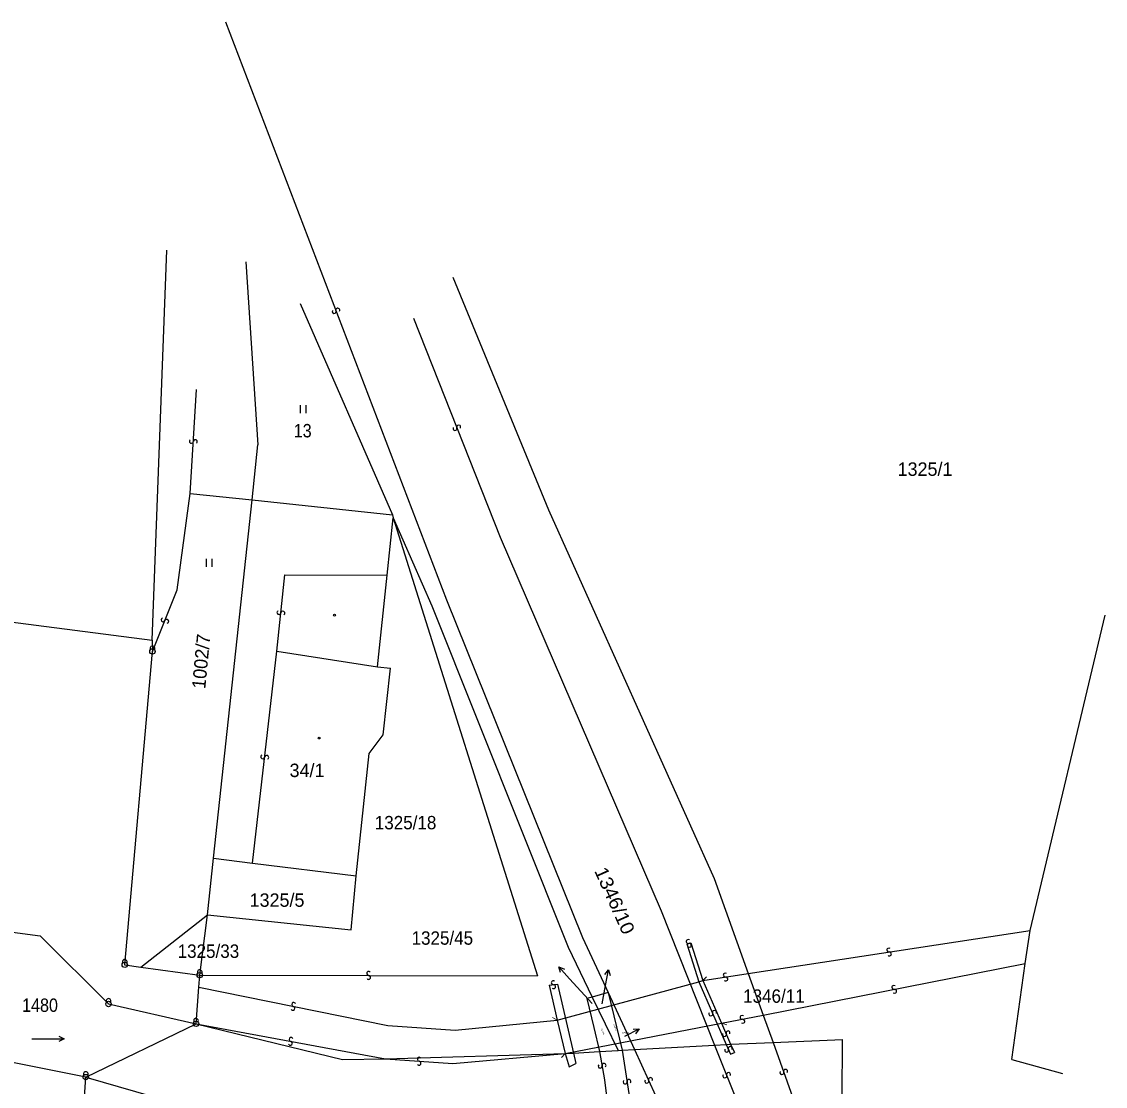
# Model space of a CAD drawing. Extents: x -871901 to -870967, y -1075952 to -1074892.
# Drawn here: x -871136.9 to -871056.1, y -1075219.4 to -1075139.9 of the extents above; entities that cross this region are included whole.
import ezdxf
from ezdxf.enums import TextEntityAlignment as Align

# ---------------------------------------------------------------- set-up
doc = ezdxf.new("R2010")
doc.units = 0
doc.header["$LTSCALE"] = 0.4
for name, color, linetype, lineweight in [('1', 7, 'Continuous', 25), ('16', 7, 'Continuous', 25), ('24', 7, 'Continuous', 25), ('25', 7, 'Continuous', 25), ('26', 7, 'Continuous', 25), ('4', 7, 'Continuous', 25)]:
    doc.layers.add(name, color=color, linetype=linetype, lineweight=lineweight)
doc.layers.add('18', color=7, linetype='Continuous')
doc.layers.add('19', color=7, linetype='Continuous')

msp = doc.modelspace()

# ---------------------------------------------------------------- linework, layer by layer
at = {"layer": '1'}
for p, q in [((-871127.17, -1075186.06), (-871126.1, -1075156.97)), ((-871120.19, -1075157.85), (-871119.29, -1075171.49)), ((-871104.75, -1075159), (-871097.61, -1075176.34)), ((-871116.14, -1075160.96), (-871109.26, -1075176.73)), ((-871119.73, -1075175.61), (-871119.29, -1075171.49)), ((-871122.61, -1075202.33), (-871119.73, -1075175.61)), ((-871119.73, -1075175.61), (-871109.26, -1075176.73)), ((-871109.64, -1075181.21), (-871109.2, -1075176.94)), ((-871097.61, -1075176.34), (-871085.24, -1075203.86)), ((-871164.62, -1075181.27), (-871127.17, -1075186.06)), ((-871110.36, -1075188.06), (-871109.64, -1075181.21)), ((-871127.17, -1075186.06), (-871127.16, -1075186.91)), ((-871129.23, -1075210.29), (-871127.16, -1075186.91)), ((-871110.36, -1075188.06), (-871109.41, -1075188.17)), ((-871109.95, -1075193.13), (-871109.41, -1075188.17)), ((-871122.61, -1075202.33), (-871119.69, -1075202.71)), ((-871119.69, -1075202.71), (-871111.95, -1075203.66)), ((-871112.34, -1075207.69), (-871111.95, -1075203.66)), ((-871085.24, -1075203.86), (-871082.7, -1075210.94)), ((-871128.02, -1075210.46), (-871123.06, -1075206.55)), ((-871123.06, -1075206.55), (-871112.34, -1075207.69)), ((-871129.23, -1075210.29), (-871128.02, -1075210.46)), ((-871128.02, -1075210.46), (-871123.63, -1075211.06)), ((-871082.7, -1075210.94), (-871081.59, -1075214.04)), ((-871123.7, -1075211.96), (-871123.63, -1075211.06)), ((-871123.91, -1075214.69), (-871123.7, -1075211.96)), ((-871093.16, -1075212.36), (-871091.2, -1075216.61)), ((-871093.16, -1075212.36), (-871092.1, -1075216.66)), ((-871081.59, -1075214.04), (-871080.85, -1075216.08)), ((-871123.91, -1075214.69), (-871112.99, -1075217.35)), ((-871091.2, -1075216.61), (-871085.21, -1075216.27)), ((-871080.85, -1075216.08), (-871075.68, -1075215.86)), ((-871112.99, -1075217.35), (-871109.77, -1075217.3)), ((-871109.77, -1075217.3), (-871096.36, -1075216.91)), ((-871096.36, -1075216.91), (-871095.74, -1075216.87)), ((-871063.04, -1075217.35), (-871059.26, -1075218.39)), ((-871132.14, -1075218.66), (-871116.67, -1075223.11))]:
    msp.add_line(p, q, dxfattribs=at)
for points in [[(-871109.26, -1075176.73), (-871109.2, -1075176.94), (-871106.32, -1075183.51), (-871096.14, -1075208.96)], [(-871063.04, -1075217.35), (-871062.03, -1075210.19), (-871061.68, -1075207.72), (-871056.06, -1075184.2)], [(-871111.95, -1075203.66), (-871110.99, -1075194.53), (-871109.95, -1075193.13)], [(-871123.63, -1075211.06), (-871123.06, -1075206.55), (-871122.61, -1075202.33)], [(-871132.14, -1075218.66), (-871140.73, -1075216.95), (-871140.23, -1075207.5)], [(-871140.23, -1075207.5), (-871135.53, -1075208.13), (-871130.44, -1075213.21), (-871123.91, -1075214.69)], [(-871096.14, -1075208.96), (-871094.34, -1075212.69), (-871092.41, -1075216.68)], [(-871093.16, -1075212.36), (-871094.34, -1075212.69), (-871094.76, -1075212.8), (-871094.22, -1075214.97), (-871093.8, -1075216.76)], [(-871132.62, -1075226.11), (-871132.14, -1075218.66), (-871123.91, -1075214.69)], [(-871095.74, -1075216.87), (-871093.8, -1075216.76), (-871092.41, -1075216.68), (-871092.1, -1075216.66), (-871091.2, -1075216.61)], [(-871085.21, -1075216.27), (-871084.34, -1075216.22), (-871084.02, -1075216.21), (-871080.85, -1075216.08)], [(-871079.27, -1075220.49), (-871075.69, -1075220.23), (-871075.68, -1075215.86)]]:
    msp.add_lwpolyline(points, dxfattribs=at)
at = {"layer": '16'}
for p, q in [((-871096.04, -1075211.33), (-871096.844, -1075210.439)), ((-871093.36, -1075211.83), (-871093.141, -1075210.65)), ((-871094.36, -1075213.18), (-871096.04, -1075211.33)), ((-871093.61, -1075213.2), (-871093.36, -1075211.83)), ((-871091.91, -1075215.62), (-871090.84, -1075215.075))]:
    msp.add_line(p, q, dxfattribs=at)
for points in [[(-871096.724, -1075210.87), (-871096.844, -1075210.439), (-871096.427, -1075210.602)], [(-871093.41, -1075211.007), (-871093.141, -1075210.65), (-871093.017, -1075211.079)], [(-871091.287, -1075215.078), (-871090.84, -1075215.075), (-871091.106, -1075215.435)]]:
    msp.add_lwpolyline(points, dxfattribs=at)
at = {"layer": '24'}
for centre, radius in [((-871127.1595, -1075186.9095), 0.2005), ((-871127.1595, -1075186.9095), 0.00851), ((-871129.2295, -1075210.2895), 0.2005), ((-871129.2295, -1075210.2895), 0.00851), ((-871123.6295, -1075211.0595), 0.2005), ((-871123.6295, -1075211.0595), 0.00851), ((-871130.4395, -1075213.2095), 0.2005), ((-871130.4395, -1075213.2095), 0.00851), ((-871123.9095, -1075214.6895), 0.2005), ((-871123.9095, -1075214.6895), 0.00851), ((-871132.1395, -1075218.6595), 0.2005), ((-871132.1395, -1075218.6595), 0.00851)]:
    msp.add_circle(centre, radius, dxfattribs=at)
for centre in [(-871127.1598, -1075186.6836), (-871129.2298, -1075210.0636), (-871123.6298, -1075210.8336), (-871130.4398, -1075212.9836), (-871123.9098, -1075214.4636), (-871132.1398, -1075218.4336)]:
    msp.add_arc(centre, 0.1746, 328.19485, 209.95045, dxfattribs=at)
at = {"layer": '25'}
for p, q in [((-871116.106, -1075169.135), (-871116.106, -1075168.535)), ((-871115.693, -1075169.135), (-871115.693, -1075168.535)), ((-871123.126, -1075180.595), (-871123.126, -1075179.995)), ((-871122.713, -1075180.595), (-871122.713, -1075179.995)), ((-871136.15, -1075215.82), (-871133.749, -1075215.82))]:
    msp.add_line(p, q, dxfattribs=at)
msp.add_lwpolyline([(-871134.149, -1075215.619), (-871133.749, -1075215.82), (-871134.149, -1075216.02)], dxfattribs=at)
for centre in [(-871113.5795, -1075184.2095), (-871114.7295, -1075193.3695)]:
    msp.add_circle(centre, 0.0705, dxfattribs=at)
for centre, radius, start, end in [((-871113.6081, -1075161.5507), 0.1471, 148.03701, 19.58833), ((-871113.3321, -1075161.4484), 0.1472, 328.13804, 200.64859), ((-871104.5876, -1075170.2723), 0.1472, 149.23847, 20.58919), ((-871104.3126, -1075170.1668), 0.1473, 328.86146, 201.15112), ((-871124.2564, -1075171.239), 0.1468, 123.81387, 355.69416), ((-871123.9626, -1075171.2605), 0.1477, 304.23097, 176.67729), ((-871117.7261, -1075184.0129), 0.147, 121.73204, 353.36129), ((-871117.4332, -1075184.0461), 0.1477, 301.43196, 173.79242), ((-871126.3658, -1075184.5539), 0.1469, 105.96952, 337.62255), ((-871126.0938, -1075184.6661), 0.1473, 285.73428, 158.14591), ((-871118.926, -1075194.7716), 0.1471, 121.47472, 352.97441), ((-871118.6337, -1075194.8084), 0.1475, 300.89976, 173.35652), ((-871087.1817, -1075208.5488), 0.1473, 54.93118, 286.58962), ((-871087.0974, -1075208.8311), 0.1474, 234.37396, 106.96356), ((-871072.2109, -1075209.1843), 0.1472, 46.66657, 278.18725), ((-871072.1685, -1075209.4759), 0.1475, 225.82417, 98.36216), ((-871111.028, -1075210.9326), 0.1474, 37.15933, 269.22266), ((-871084.4209, -1075211.0543), 0.1472, 46.66657, 278.18725), ((-871111.0311, -1075211.2275), 0.1475, 217.02669, 89.61382), ((-871097.2547, -1075211.6235), 0.1472, 43.98721, 275.82854), ((-871097.2251, -1075211.9166), 0.1474, 223.34947, 95.58775), ((-871084.3785, -1075211.3459), 0.1475, 225.82417, 98.36216), ((-871071.8363, -1075211.9753), 0.1471, 48.43878, 280.16792), ((-871071.7831, -1075212.2649), 0.1474, 228.30368, 100.3659), ((-871116.6811, -1075213.5341), 0.1474, 205.69864, 77.85438), ((-871116.6194, -1075213.2461), 0.1471, 25.80808, 257.85296), ((-871085.4957, -1075213.9471), 0.1472, 150.64344, 22.70345), ((-871085.2246, -1075213.8321), 0.1473, 330.94838, 203.25141), ((-871083.1663, -1075214.2053), 0.1471, 48.43878, 280.16792), ((-871083.1131, -1075214.4949), 0.1474, 228.30368, 100.3659), ((-871116.8117, -1075215.8553), 0.1474, 26.99346, 259.07257), ((-871084.4859, -1075215.4869), 0.1474, 150.30454, 22.00339), ((-871084.2143, -1075215.3722), 0.1475, 330.40612, 203.09844), ((-871116.8686, -1075216.1444), 0.1472, 207.08914, 79.17619), ((-871084.3159, -1075216.6469), 0.1474, 150.30454, 22.00339), ((-871084.0446, -1075216.5321), 0.1473, 330.94838, 203.25141), ((-871107.2478, -1075217.3331), 0.1474, 33.57583, 265.33525), ((-871107.272, -1075217.627), 0.1475, 212.83023, 85.33669), ((-871093.7555, -1075217.8427), 0.1473, 137.20369, 8.0804), ((-871093.465, -1075217.795), 0.1472, 317.07802, 189.78392), ((-871080.1993, -1075218.3277), 0.1472, 147.17263, 18.35746), ((-871079.9209, -1075218.2313), 0.1474, 326.99271, 199.42006), ((-871091.8962, -1075219.0298), 0.1475, 135.82345, 7.13823), ((-871091.6042, -1075218.9889), 0.1473, 314.90348, 188.18653), ((-871090.2745, -1075218.9699), 0.1472, 151.70045, 23.42411), ((-871090.0055, -1075218.8494), 0.1475, 332.35817, 204.47779), ((-871084.4476, -1075218.5823), 0.1472, 149.23847, 20.58919), ((-871084.1726, -1075218.4768), 0.1473, 328.86146, 201.15112)]:
    msp.add_arc(centre, radius, start, end, dxfattribs=at)
at = {"layer": '26', "lineweight": 13}
for p, q in [((-871085.809, -1075211.18), (-871086.09, -1075211.46)), ((-871097.302, -1075214.23), (-871096.95, -1075214.41)), ((-871084.313, -1075214.772), (-871084.69, -1075214.65)), ((-871096.64, -1075217.19), (-871096.36, -1075216.91))]:
    msp.add_line(p, q, dxfattribs=at)
at = {"layer": '4'}
for p, q in [((-871121.72, -1075139.93), (-871105.23, -1075183.06)), ((-871107.69, -1075162.06), (-871101.22, -1075178.38)), ((-871124.35, -1075175.12), (-871119.73, -1075175.61)), ((-871109.2, -1075176.94), (-871098.43, -1075211.1)), ((-871101.22, -1075178.38), (-871089.2, -1075206.25)), ((-871105.23, -1075183.06), (-871095.06, -1075208.25)), ((-871119.69, -1075202.71), (-871117.87, -1075186.88)), ((-871117.87, -1075186.88), (-871110.36, -1075188.06)), ((-871089.2, -1075206.25), (-871085.21, -1075216.27)), ((-871082.7, -1075210.94), (-871061.68, -1075207.72)), ((-871095.06, -1075208.25), (-871093.16, -1075212.36)), ((-871087.28, -1075208.73), (-871086.99, -1075208.64)), ((-871087.28, -1075208.73), (-871086.38, -1075211.55)), ((-871086.99, -1075208.64), (-871086.09, -1075211.46)), ((-871086.09, -1075211.46), (-871082.7, -1075210.94)), ((-871081.59, -1075214.04), (-871062.03, -1075210.19)), ((-871123.63, -1075211.06), (-871098.43, -1075211.1)), ((-871097.55, -1075211.81), (-871096.93, -1075211.74)), ((-871096.93, -1075211.74), (-871095.74, -1075216.87)), ((-871086.38, -1075211.55), (-871084.34, -1075216.22)), ((-871086.09, -1075211.46), (-871084.69, -1075214.65)), ((-871123.7, -1075211.96), (-871109.59, -1075214.81)), ((-871084.69, -1075214.65), (-871081.59, -1075214.04)), ((-871123.91, -1075214.69), (-871109.77, -1075217.3)), ((-871109.59, -1075214.81), (-871104.57, -1075215.17)), ((-871104.57, -1075215.17), (-871096.95, -1075214.41)), ((-871096.36, -1075216.91), (-871084.69, -1075214.65)), ((-871084.69, -1075214.65), (-871084.02, -1075216.21)), ((-871091.2, -1075216.61), (-871089.08, -1075221.2)), ((-871085.21, -1075216.27), (-871083.4, -1075220.8)), ((-871084.02, -1075216.21), (-871083.74, -1075216.84)), ((-871080.85, -1075216.08), (-871079.27, -1075220.49)), ((-871109.77, -1075217.3), (-871104.75, -1075217.66)), ((-871104.75, -1075217.66), (-871096.36, -1075216.91)), ((-871095.74, -1075216.87), (-871095.56, -1075217.65)), ((-871092.1, -1075216.66), (-871091.39, -1075221.36))]:
    msp.add_line(p, q, dxfattribs=at)
for points in [[(-871127.16, -1075186.91), (-871125.31, -1075182.31), (-871124.35, -1075175.12), (-871123.88, -1075167.38)], [(-871117.87, -1075186.88), (-871117.29, -1075181.19), (-871109.64, -1075181.21)], [(-871096.95, -1075214.41), (-871086.38, -1075211.55), (-871086.09, -1075211.46)], [(-871097.55, -1075211.81), (-871096.95, -1075214.41), (-871096.36, -1075216.91)], [(-871084.34, -1075216.22), (-871084.02, -1075216.96), (-871083.74, -1075216.84)], [(-871096.36, -1075216.91), (-871096.07, -1075217.9), (-871095.56, -1075217.65)], [(-871093.8, -1075216.76), (-871093.43, -1075218.88), (-871093.1, -1075221.48)]]:
    msp.add_lwpolyline(points, dxfattribs=at)

# ---------------------------------------------------------------- texts
at = {"layer": '16', "width": 1.1}
msp.add_text('1346/10', height=1, rotation=294.102, dxfattribs=at).set_placement((-871093.1233, -1075205.7013), align=Align.CENTER)
at = {"layer": '16', "width": 0.95}
for s, p in [('1325/45', (-871105.53, -1075208.79)), ('1346/11', (-871080.79, -1075213.12))]:
    msp.add_text(s, height=1, dxfattribs=at).set_placement(p, align=Align.CENTER)
at = {"layer": '18'}
for s, width, p in [('13', 0.9, (-871116.62, -1075170.94)), ('1325/18', 0.95, (-871110.57, -1075200.18)), ('1325/33', 0.95, (-871125.28, -1075209.77)), ('1480', 0.9, (-871136.89, -1075213.8))]:
    msp.add_text(s, height=1, dxfattribs=dict(at, width=width)).set_placement(p)
for s, p in [('1325/1', (-871071.56, -1075173.81)), ('1325/5', (-871119.91, -1075205.96))]:
    msp.add_text(s, height=1, dxfattribs=at).set_placement(p)
msp.add_text('1002/7', height=1, rotation=84.601, dxfattribs=at).set_placement((-871123.22, -1075189.733))
at = {"layer": '18', "width": 1.1}
for s, rotation, p in [('1325/45', 291.702, (-871093.6089, -1075215.2835)), ('1346/10', 293.602, (-871092.7023, -1075214.9665))]:
    msp.add_text(s, height=0.1, rotation=rotation, dxfattribs=at).set_placement(p, align=Align.CENTER)
at = {"layer": '18', "width": 0.95}
msp.add_text('1346/11', height=0.1, dxfattribs=at).set_placement((-871091.85, -1075215.39), align=Align.CENTER)
at = {"layer": '19'}
msp.add_text('34/1', height=1, dxfattribs=at).set_placement((-871116.93, -1075196.28))

doc.saveas('drawing.dxf')
